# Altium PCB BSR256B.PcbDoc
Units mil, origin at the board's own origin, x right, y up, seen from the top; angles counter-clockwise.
Board outline 2710.5 x 1796.5 mil, 4 copper layers (Top Layer, Signal Layer 1, Signal Layer 2, Bottom Layer), stack 60.434 mil thick; 46 components, 13 nets, 68 pads, 21 vias.
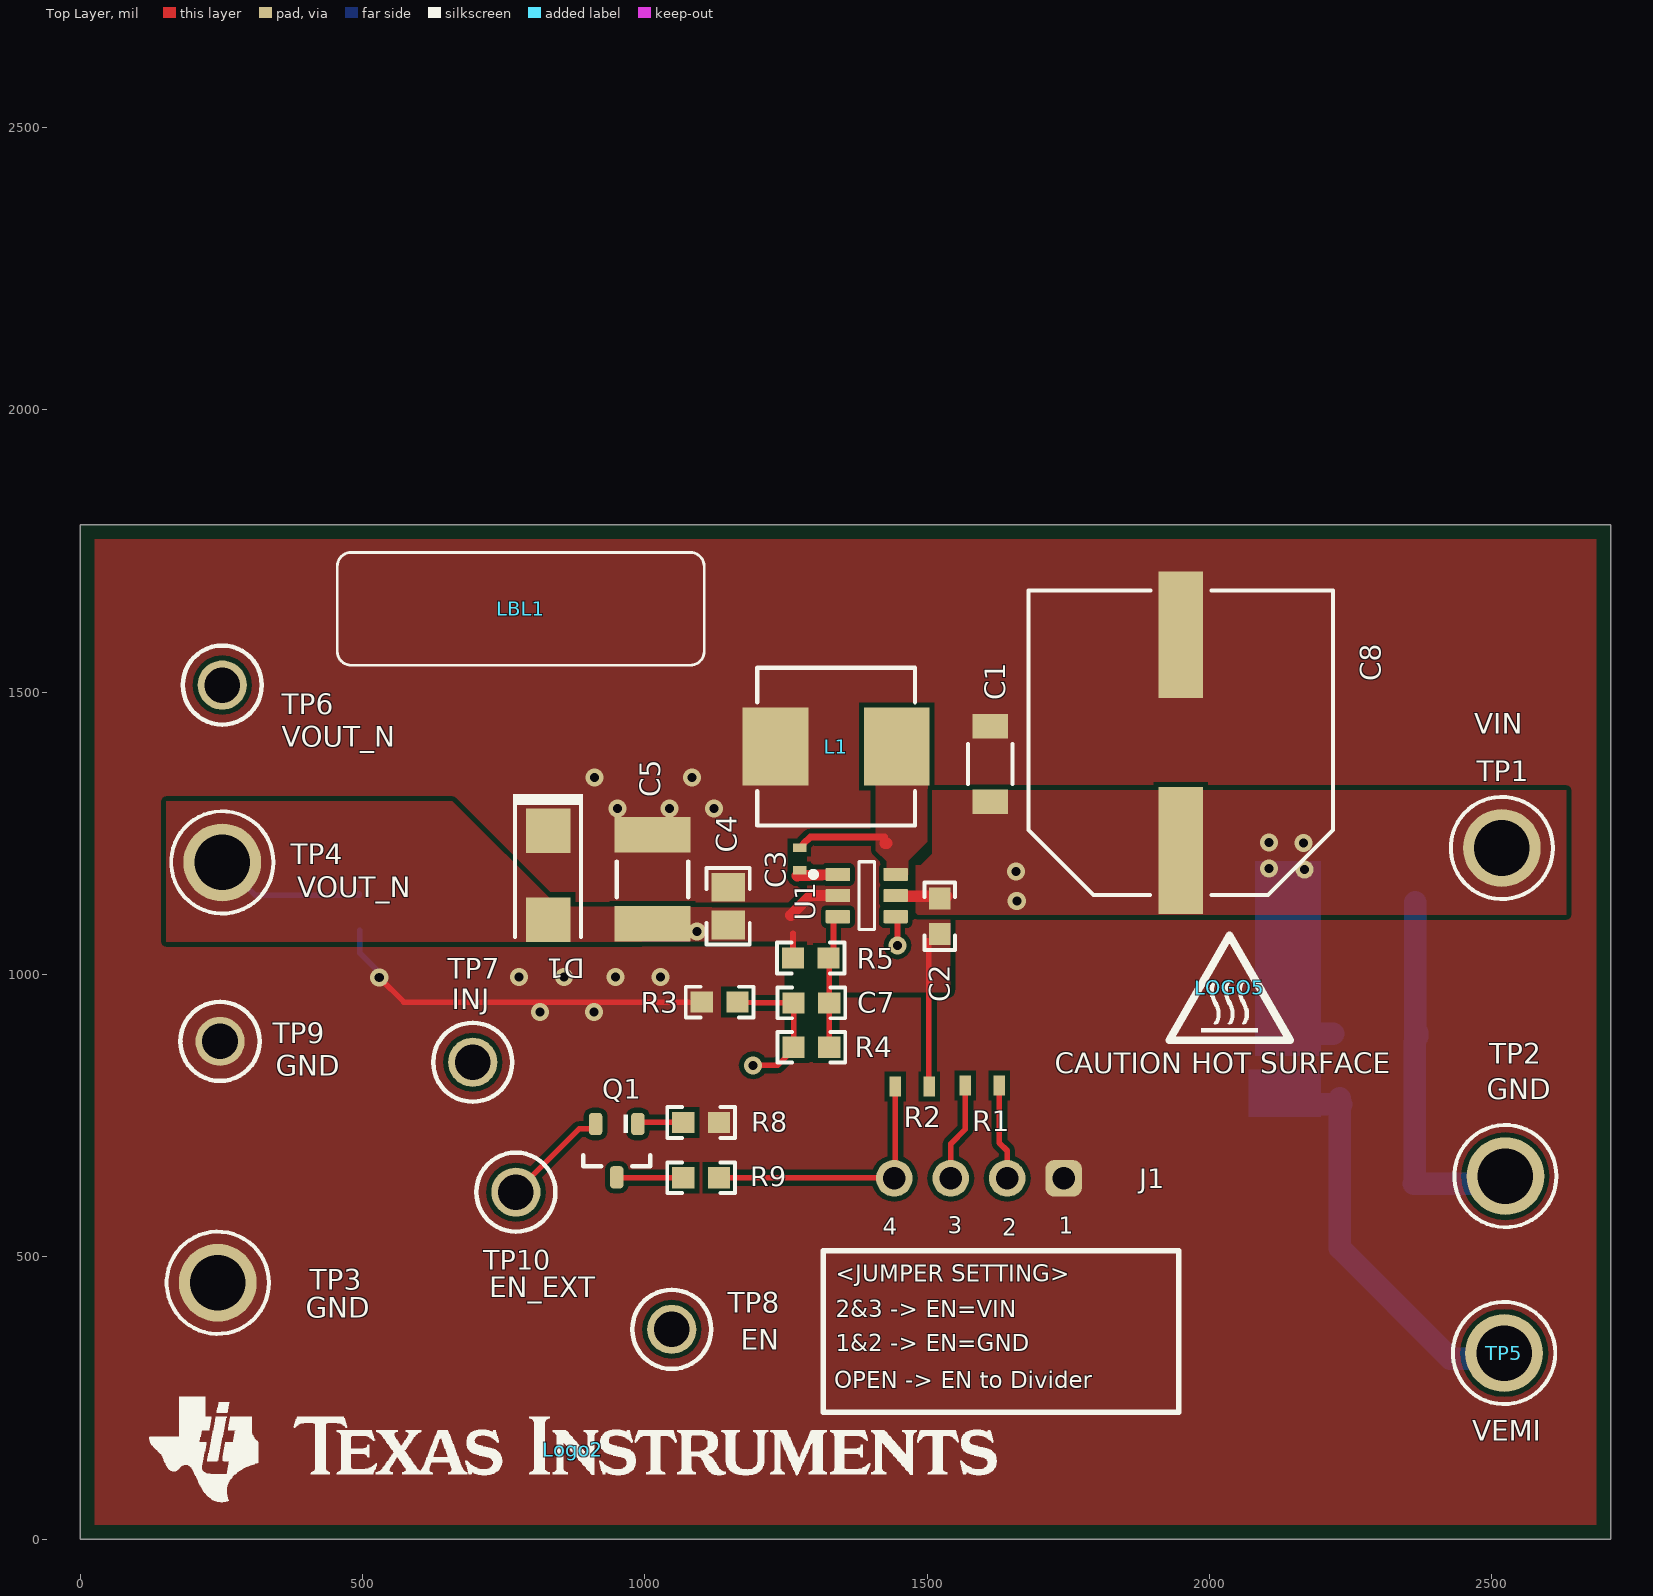
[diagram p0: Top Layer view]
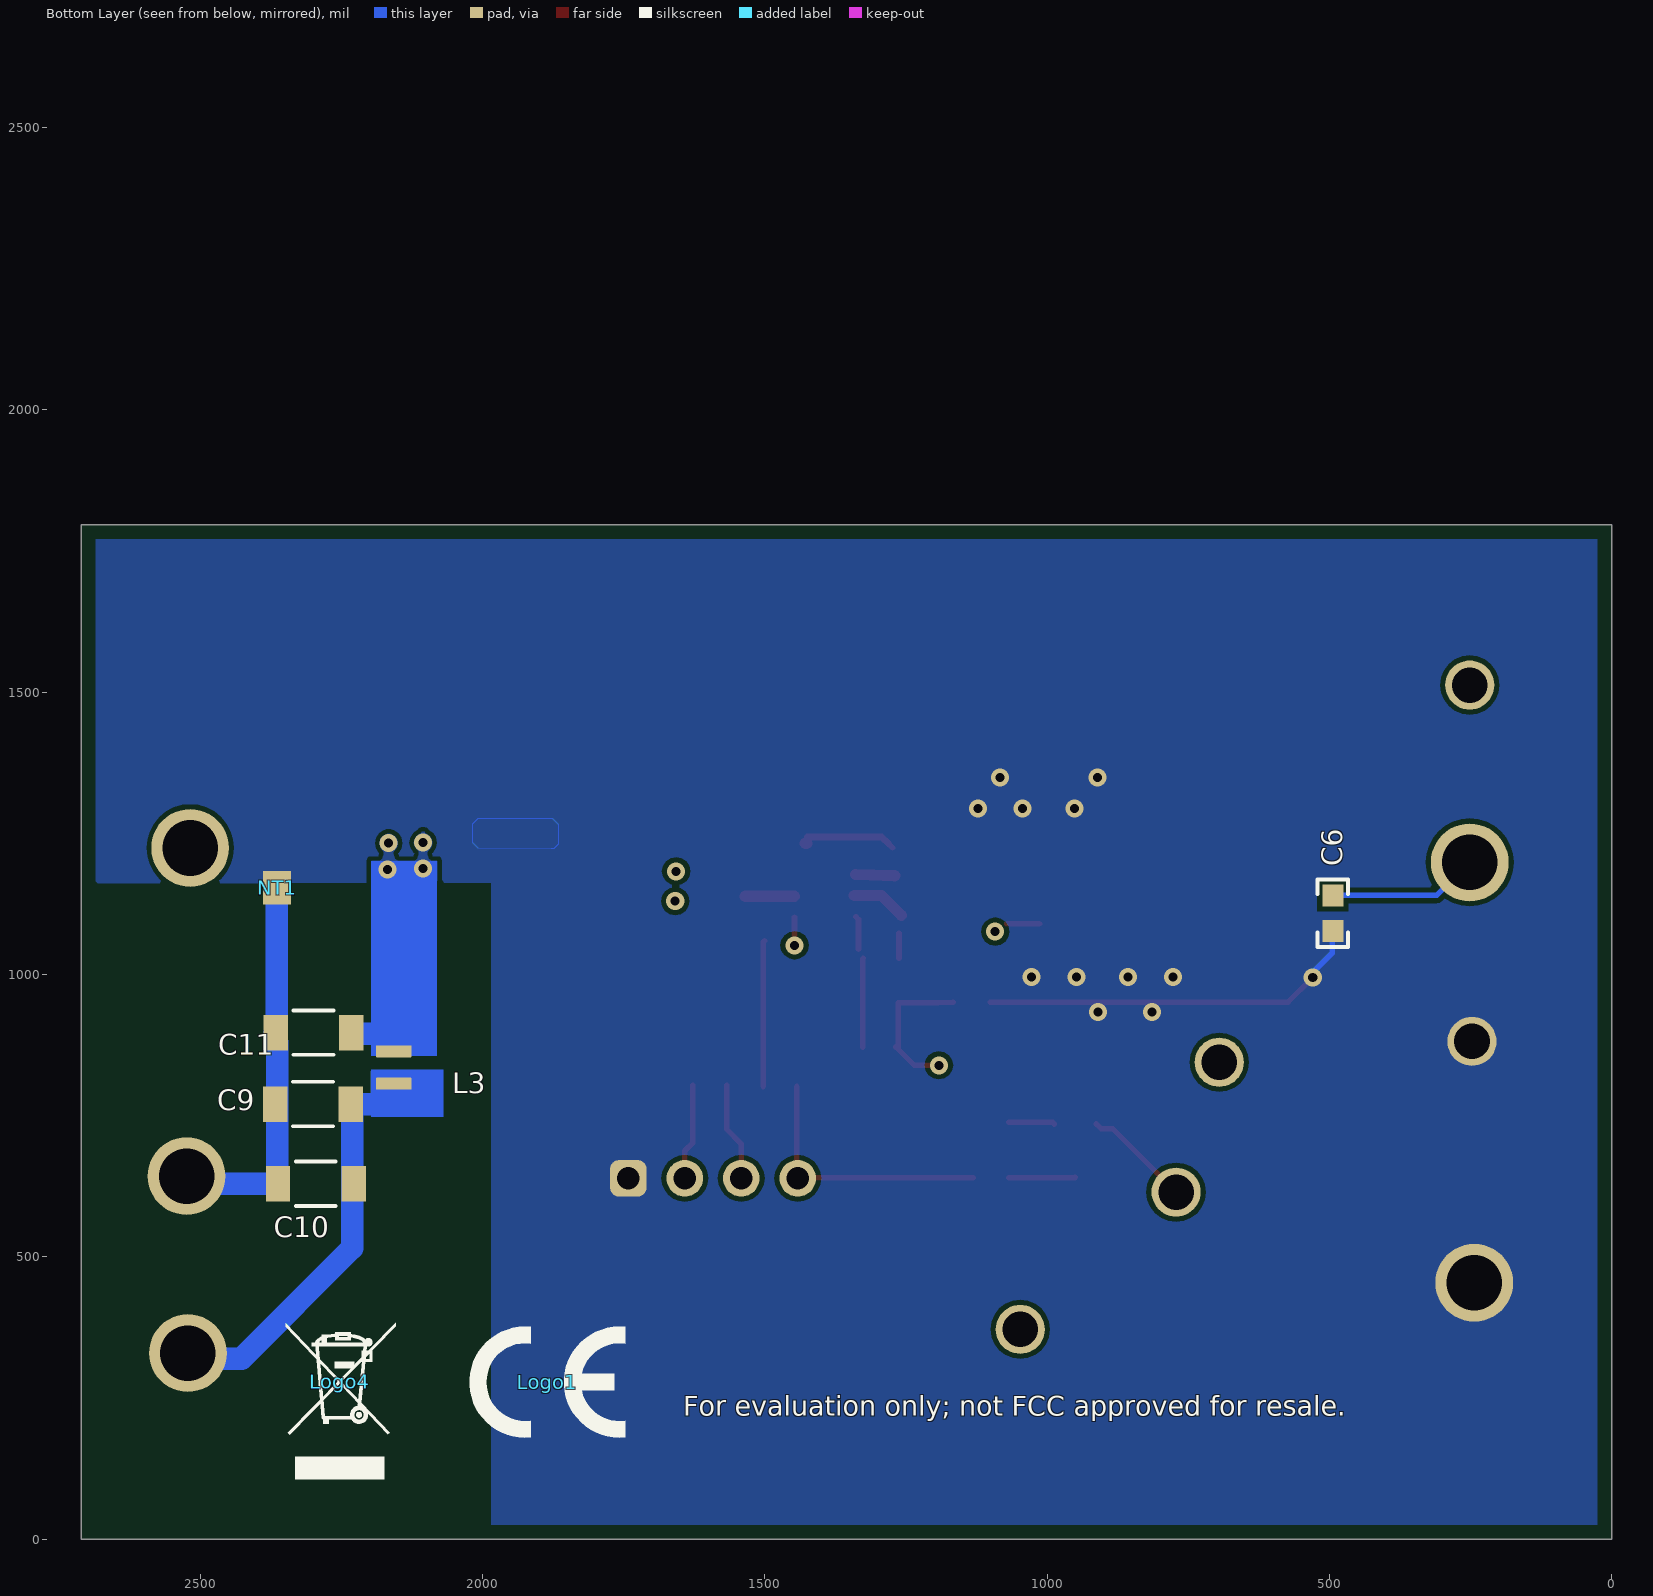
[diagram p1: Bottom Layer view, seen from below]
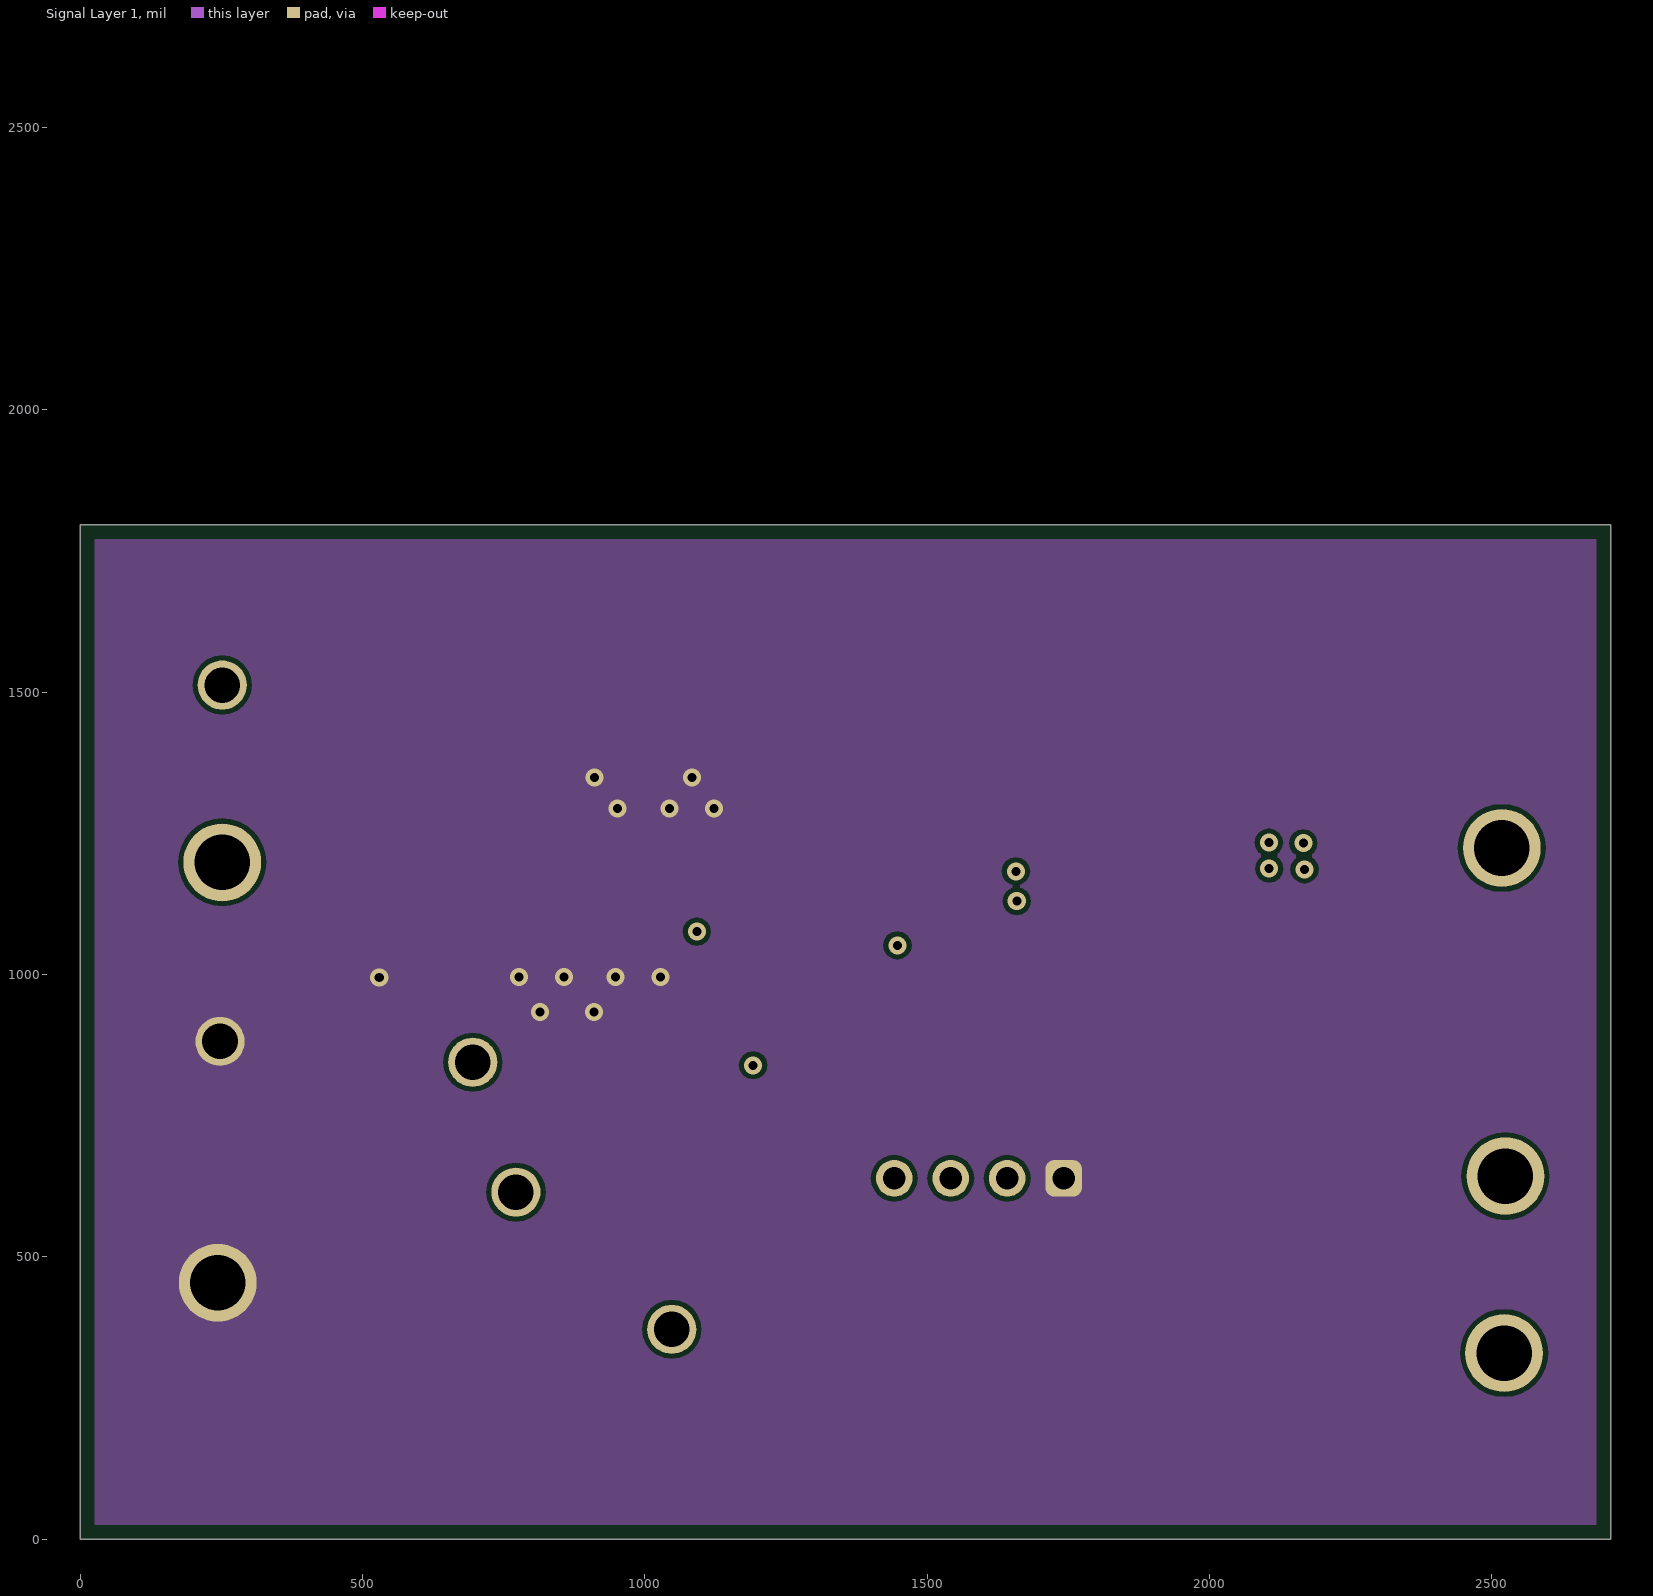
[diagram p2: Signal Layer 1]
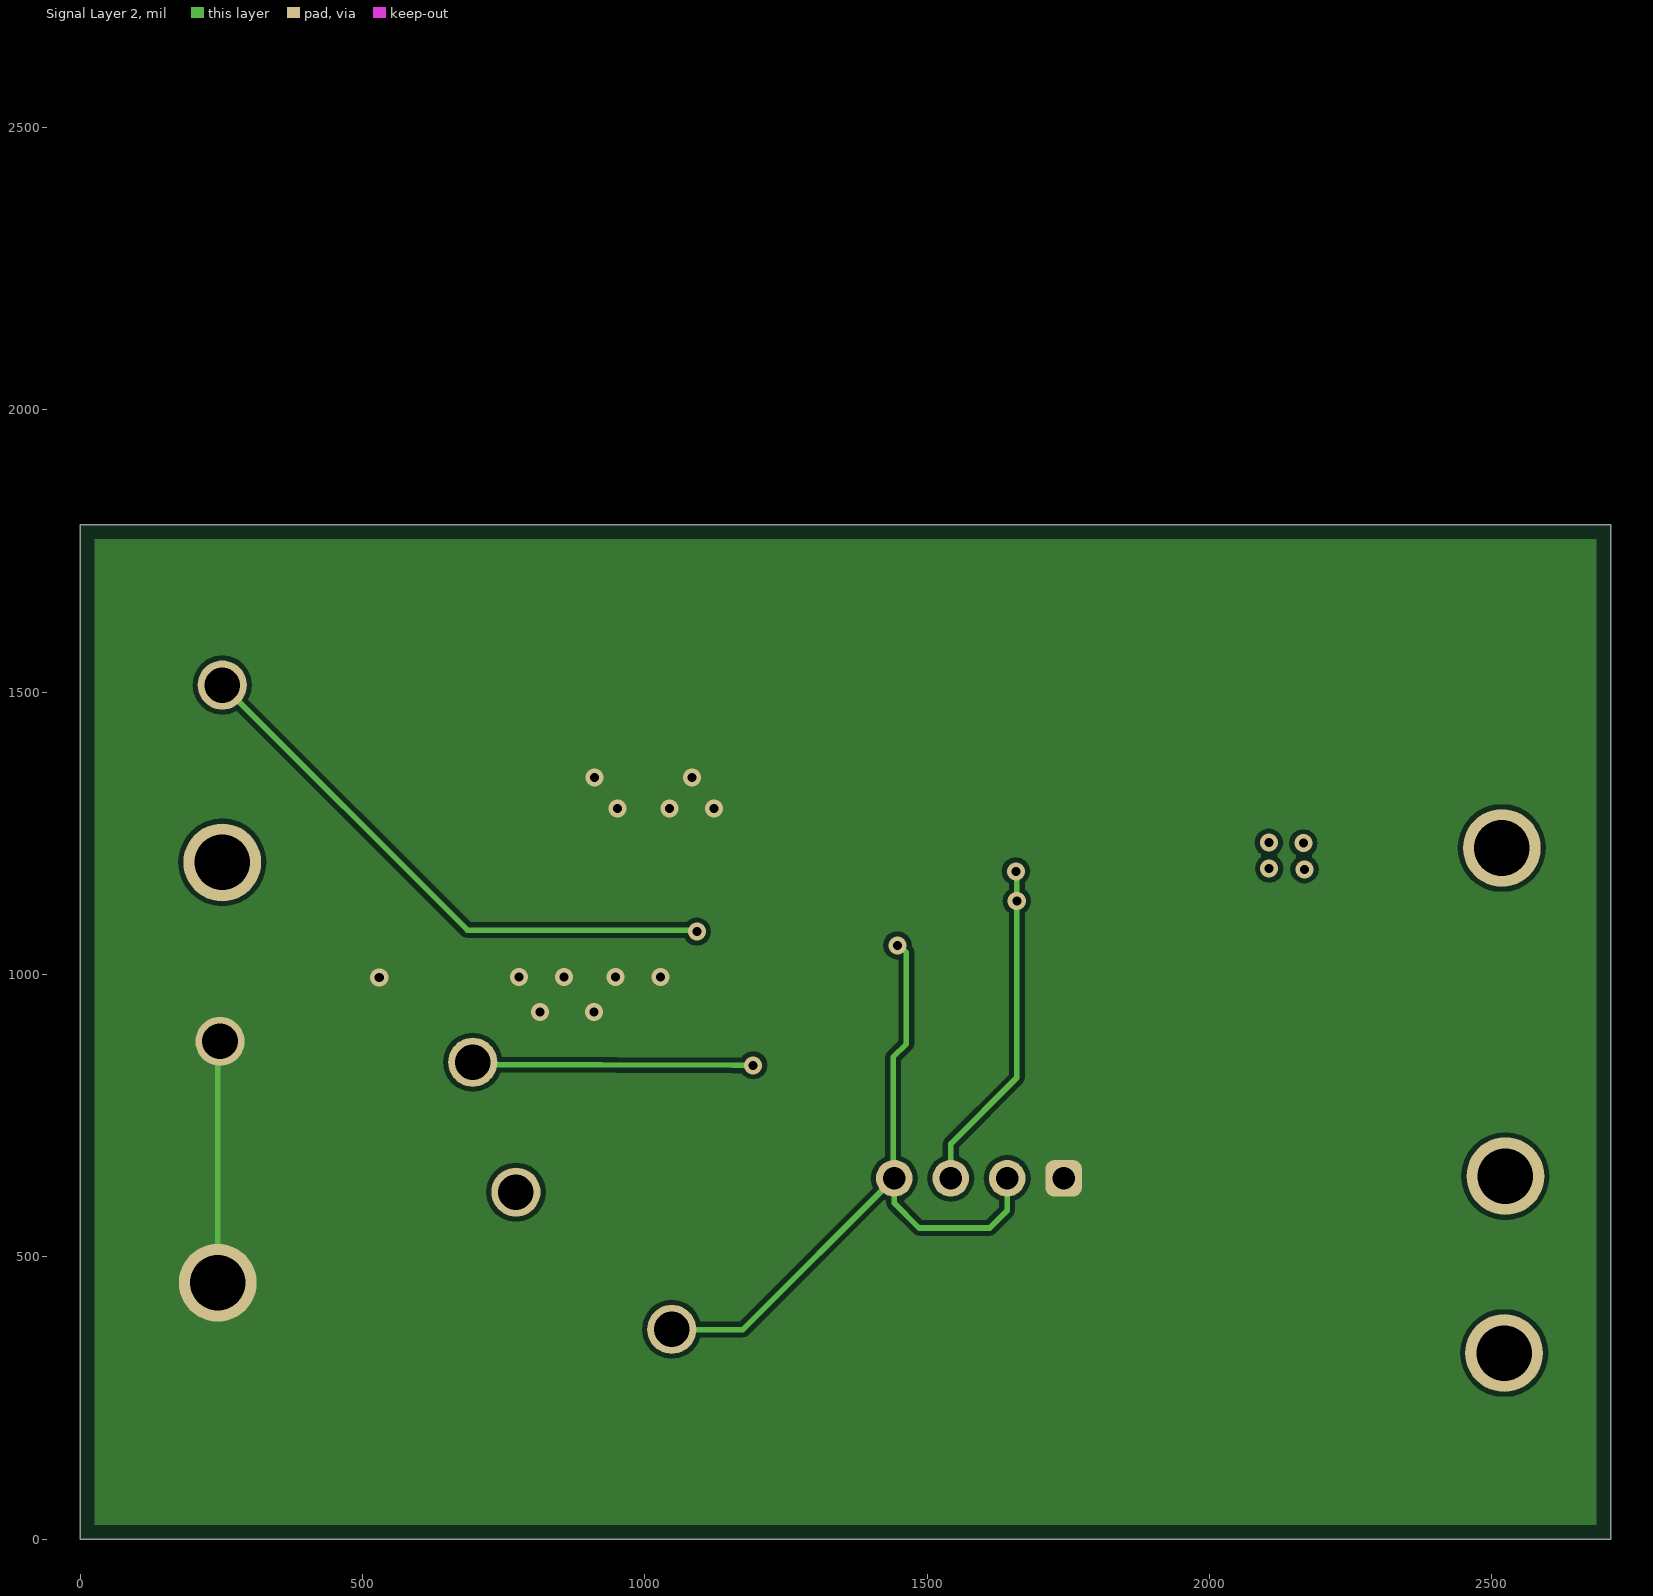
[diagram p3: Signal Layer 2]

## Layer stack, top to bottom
Top Solder: solder mask 0.4, Solder Resist, Dk 3.5
Top Layer: signal copper 2.8
Dielectric1: core 10, FR-4 High Tg, Dk 4.8
Signal Layer 1: signal copper 1.417
Dielectric 2: dielectric 32, FR-4 High Tg, Dk 4.2
Signal Layer 2: signal copper 1.417
Dielectric 3: dielectric 10, FR-4 High Tg, Dk 4.2
Bottom Layer: signal copper 2.8
Bottom Solder: solder mask 0.4, Solder Resist, Dk 3.5

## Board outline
0,0 0,1796.5 2710.5,1796.5 2710.5,0

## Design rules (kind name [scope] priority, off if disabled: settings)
AcuteAngle [All] p1: minimum=4.50000000000000E+0001 checktracksonly=FALSE
AssemblyTestPointUsage [All] p1: valid=2
BoardOutlineClearance BoardOutlineClearance_MountingHoles [OnCopper and InComponentClass('Mounting Holes')] p1: gap=40 ignorepadtopadclearanceinfootprint=FALSE
BoardOutlineClearance BoardOutlineClearance_Poly [OnCopper and IsPoly] p2: gap=25 ignorepadtopadclearanceinfootprint=FALSE
BoardOutlineClearance [OnCopper and Not InComponentClass('Logo') and not InComponentClass('FiducialMark') and not InRegion(1000,500,4000,800) and not InPoly] p3: gap=75 ignorepadtopadclearanceinfootprint=FALSE
Clearance Clearance_Keepouts [((IsTrack Or IsArc) And Not InPoly) And IsFree and IsKeepOut vs ((IsTrack Or IsArc) And Not InPoly) And IsFree and IsKeepOut] p1: gap=7 ignorepadtopadclearanceinfootprint=FALSE
Clearance Clearance_Poly [InPolygon] p2: gap=8.5 ignorepadtopadclearanceinfootprint=FALSE except(0: Arc-Hole Track-Hole SMDPad-Hole THPad-Hole Via-Hole Fill-Hole Poly-Hole Region-Hole Text-Hole)
Clearance [All] p3: gap=7 ignorepadtopadclearanceinfootprint=FALSE except(0: Arc-Arc Arc-Track Arc-SMDPad Arc-THPad Arc-Via Arc-Fill Arc-Poly Arc-Region Arc-Text Arc-Hole)
ComponentClearance ComponentClearance_MountingHoles_FiducialMarks [InComponentClass('Mounting Holes') vs InComponentClass('FiducialMark')] p1: gap=50 collisioncheckmode=3 verticalgap=10 showdistances=FALSE
ComponentClearance ComponentClearance_Shunt [InComponentClass('Header') vs InComponentClass('Shunt')] p2: gap=0 collisioncheckmode=3 verticalgap=0 showdistances=FALSE
ComponentClearance ComponentClearance_Logo [InComponentClass('Logo')] p3: gap=50 collisioncheckmode=3 verticalgap=10 showdistances=FALSE
ComponentClearance ComponentClearance_ScrewToNut [(HasFootprint('NY PMS 440 0025 PH')) vs (HasFootprint('Keystone_1902C'))] p4: gap=5 collisioncheckmode=3 verticalgap=10 showdistances=FALSE
ComponentClearance ComponentClearance_MountingHoles [InComponentClass('Mounting Holes')] p5: gap=250 collisioncheckmode=3 verticalgap=100000 showdistances=FALSE
ComponentClearance ComponentClearance_SmallPassives [HasFootprint('0201*') or HasFootprint('0402*') or HasFootprint('0508') or HasFootprint('0603*') or HasFootprint('0612') or HasFootprint('0805*') or HasFootprint('0815*') or HasFootprint('0830*') or HasFootprint('1206*') or HasFootprint('1210*') or HasFootprint('1808*') or HasFootprint('1812*') or HasFootprint('1825*') or HasFootprint('2010*') or HasFootprint('2220*') or HasFootprint('2225*') or HasFootprint('2512*') or HasFootprint('2728*') or HasFootprint('3518*') vs HasFootprint('0201*') or HasFootprint('0402*') or HasFootprint('0508') or HasFootprint('0603*') or HasFootprint('0612') or HasFootprint('0805*') or HasFootprint('0815*') or HasFootprint('0830*') or HasFootprint('1206*') or HasFootprint('1210*') or HasFootprint('1808*') or HasFootprint('1812*') or HasFootprint('1825*') or HasFootprint('2010*') or HasFootprint('2220*') or HasFootprint('2225*') or HasFootprint('2512*') or HasFootprint('2728*') or HasFootprint('3518*')] p6: gap=14.96 collisioncheckmode=3 verticalgap=10 showdistances=FALSE
ComponentClearance ComponentClearance_THtoSMT [IsThruComponent vs IsSMTComponent] p7: gap=10 collisioncheckmode=3 verticalgap=30 showdistances=FALSE
ComponentClearance ComponentClearance_THtoTH [IsThruComponent vs IsThruComponent] p8: gap=30 collisioncheckmode=3 verticalgap=30 showdistances=FALSE
ComponentClearance [All] p9: gap=30 collisioncheckmode=3 verticalgap=10 showdistances=FALSE
DiffPairsRouting [All] p1: maxlimit=100 minlimit=10 mostfreqgap=10 toplayer_minwidth=15 toplayer_maxwidth=15 toplayer_prefwidth=15 midlayer1_minwidth=15 midlayer1_maxwidth=15 midlayer1_prefwidth=15 midlayer2_minwidth=15 midlayer2_maxwidth=15 midlayer2_prefwidth=15 bottomlayer_minwidth=15 bottomlayer_maxwidth=15 bottomlayer_prefwidth=15 maxuncoupledlength=1000
FabricationTestPointUsage TestPointUsage [All] p1: valid=2 allowmultiple=FALSE
FabricationTestpoint Testpoint [All] p1: side=3 testpointundercomponent=TRUE minsize=40 maxsize=100 preferedsize=60 minholesize=0 maxholesize=40 preferedholesize=32 testpointgrid=1 allowsidetop=TRUE allowsidebottom=TRUE usegrid=TRUE gridtolerance=0.01
FanoutControl Fanout_LCC [IsLCC] p1: bgadir=Out bgaviamode=Centered fanoutstyle=Auto fanoutdirection=Alternating viagrid=1 // Fanout_LCC (Default Rule)
FanoutControl Fanout_BGA [IsBGA] p2: bgadir=Out bgaviamode=Centered fanoutstyle=Auto fanoutdirection=Alternating viagrid=1 // Fanout_BGA (Default Rule)
FanoutControl Fanout_Default [All] p4: bgadir=Out bgaviamode=Centered fanoutstyle=Auto fanoutdirection=Alternating viagrid=1 // Fanout_Default (Default Rule)
FanoutControl Fanout_Small [(CompPinCount < 5)] p5: bgadir=Out bgaviamode=Centered fanoutstyle=Auto fanoutdirection=OutThenIn viagrid=1 // Fanout_Small (Default Rule)
HoleSize [All] p1: absolutevalues=TRUE maxlimit=251 minlimit=7.87 maxpercent=80.000 minpercent=20.000
MinimumAnnularRing MinimumAnnularRing_ThermalPadVias [IsVia and InAnyComponent] p1: minimumring=5.91
MinimumAnnularRing [All] p2: minimumring=8
MinimumSolderMaskSliver MinimumSolderMaskSliver_Logo [InComponentClass('Logo') vs InComponentClass('Logo')] p1: minsoldermaskwidth=0.7
MinimumSolderMaskSliver [All] p2: minsoldermaskwidth=3.94
PlaneClearance [All] p1: clearance=0
PlaneConnect [All] p1: planeconnectstyle=Direct reliefexpansion=10 reliefentries=2 reliefconductorwidth=10 reliefairgap=10
PolygonConnect [All] p1: connectstyle=Direct reliefconductorwidth=10 reliefentries=4 polygonreliefangle="90 Angle" airgapwidth=10
RoutingVias ThermalPadVias [IsVia and InAnyComponent] p1: holewidth=7.87 width=19.68 viastyle="Through Hole" minholewidth=7.87 minwidth=19.68 maxholewidth=12.99 maxwidth=23.62
RoutingVias [All] p2: holewidth=16 width=34 viastyle="Through Hole" minholewidth=7.87 minwidth=26 maxholewidth=40 maxwidth=65
SilkToBoardRegionClearance [Not ((IsComment or IsDesignator) And (Hide <> 'False')) and not InRegion(1000,500,4000,800)] p1:
SilkToSilkClearance SilkToSilkClearance_Pb-FreeLogo [(HasFootprint('Pb-Free_Overlay_Medium') OR HasFootprint('Pb-Free_Overlay_Small')) vs (HasFootprint('Pb-Free_Overlay_Medium') OR HasFootprint('Pb-Free_Overlay_Small'))] p1: silktosilkclearance=0
SilkToSilkClearance [All] p2: silktosilkclearance=4
SilkToSolderMaskClearance SilkToComponentPadClearance [(IsPad or IsFill or IsRegion) and InAnycomponent] p1: minsilkscreentomaskgap=2 clearancetoexposedcopper=TRUE
SilkToSolderMaskClearance "Silk to Solder Mask Opening" [All] p2: minsilkscreentomaskgap=0.5 clearancetoexposedcopper=TRUE
SolderMaskExpansion [All] p1: expansion=1.85
Width [All] p1: maxlimit=100 minlimit=3 preferedwidth=10 midlayer1_minwidth=6 midlayer2_minwidth=6 bottomlayer_minwidth=6 minimp=50.000000 maximp=50.000000 favimp=50.000000 checkconnectedcopper=TRUE
14 further rules are at their usual default settings.

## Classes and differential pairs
component class BSR256B: C1 C2 C3 C4 C5 C6 C7 C8 C9 C10 C11 D1 J1 L1 L3 NT1 Q1 R1 R2 R3 R4 R5 R8 R9 TP1 TP2 TP3 TP4 TP5 TP6 TP7 TP8 TP9 TP10 U1
component class Label: LBL1
component class BSR256B_Hardware: LBL1 Logo1 Logo2 Logo3 Logo4 LOGO5 LOGO7 ZZ1 ZZ2 ZZ3 ZZ4 ZZ5
component class Logo: Logo2
component class Header: J1
component class AssemblyNote: ZZ1 ZZ2 ZZ3 ZZ4 ZZ5

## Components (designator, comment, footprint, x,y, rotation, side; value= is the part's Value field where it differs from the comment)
C1 "C3216X7S2A225K160AB" 1206_180 1611.5,1372.5 r90 top value=2.2uF
C2 "GRM188R72A104KA35J" 0603 1522,1103.14 r270 top value=0.1uF
C3 "GRM155R71E104KE14D" 0402S 1273.81,1204.5 r270 top value=0.1uF
C4 "GRM21BZ71E106KE15L" 0805 1147.5,1120.96 r270 top value=10uF
C5 "CGA8P1X7R1E226M250KC" 1812_280 1013.31,1168.5 r270 top value=22uF
C6 "C1608X7R1H104K080AA" 0603 493.93,1108.5 r90 bottom value=0.1uF
C7 "CGA3E2C0G1H220J080AA" 0603 1294.72,949.6 r0 top value=22pF
C8 "EEV-TG2A470Q" Panasonic_H13 1949,1410.5 r90 top value=47uF
C9 "C3216X7S2A225K160AB" 1206_180 2300.03,770.5 r0 bottom value=2.2uF
C10 "C3216X7S2A225K160AB" 1206_180 2295.03,629.24 r0 bottom value=2.2uF
C11 "C3216X7S2A225K160AB" 1206_180 2299.1,897 r0 bottom value=2.2uF
D1 "B260A-13-F" SMA 828.5,1176 r270 top value=60V
J1 "TSW-104-07-G-S" TSW-104-07-G-S 1591.52,639 r180 top
L1 "74437349150" WE-LHMI_7050 1338.5,1403.5 r180 top value=15uH
L3 "DFE201612E-1R0M=P2" DFE201612E 2157.03,835.24 r90 bottom value=1uH
LBL1 "THT-14-423-10" Label_650x200 780,1647.5 r0 top
Logo1 "CE Mark" CE_Mark_5mm 1885,278 r180 bottom
Logo2 "Texas Instruments" TI_Horizontal_Overlay_Medium 872.5,158.5 r0 top
Logo3 "FCC disclaimer" FCC_disclaimer -358.76,747 r90 bottom
Logo4 "WEEE logo" WEEE_Minimum 2252.5,278.5 r180 bottom
LOGO5 "CAUTION HOT SURFACE" IEC_HotSurface_Small 2035.5,976.5 r0 top
NT1 "Net-Tie" Net-Tie_50milWide_30milLong 2363.5,1153.5 r90 bottom net-tie
Q1 "CMPT3906 LEAD FREE" SOT-23 950,688 r270 top value="40 V"
R1 "CRCW0603402KFKEA" 0603S 1597.5,803.5 r180 top value=402k
R2 "CRCW0603133KFKEA" 0603S 1473.5,801.5 r0 top value=133k
R3 "Resistor" 0603 1132.22,950.99 r0 top value=49.9
R4 "CRCW060388K7FKEA" 0603 1294.72,871.17 r180 top value=88.7k
R5 "RC0603FR-0722K1L" 0603 1293.7,1029 r0 top value=22.1k
R8 "ERJ-3EKF1002V" 0603 1099.5,738 r180 top value=10.0k
R9 "ERJ-3EKF1002V" 0603 1099.5,640 r180 top value=10.0k
TP1 "1502-2" Keystone1502-2 2517.5,1224 r0 top
TP2 "1502-2" Keystone1502-2 2523.77,642.8 r0 top
TP3 "1502-2" Keystone1502-2 243.5,454 r0 top
TP4 "1502-2" Keystone1502-2 251.5,1198.5 r0 top
TP5 "1502-2" Keystone1502-2 2521.5,329.5 r0 top
TP6 "5010" Keystone5010 251.5,1512.5 r0 top
TP7 "5014" Keystone5014 695,844.5 r0 top
TP8 "5014" Keystone5014 1047.5,371.5 r0 top
TP9 "5011" Keystone5011 247.5,881.5 r0 top
TP10 "5014" Keystone5014 771.5,614.5 r0 top
U1 "LMR51610DBVR" DBV0006A-MFG 1392.84,1139.74 r0 top
ZZ1 "This Assembly Note is for PCB labels only" AssemblyNoteLabel 197,3292.5 r0 top
ZZ2 "These assemblies are ESD sensitive, ESD precautions shall be observed." AssemblyNote 197,3169.5 r0 top
ZZ3 "These assemblies must be clean and free from flux and all contaminants. Use of no clean flux is not acceptable." AssemblyNote 197,3046 r0 top
ZZ4 "These assemblies must comply with workmanship standards IPC-A-610 Class 2, unless otherwise specified." AssemblyNote 197,2913.5 r0 top
ZZ5 "SH-J1 should be put in the 2 & 3 pin of JP1 by default." AssemblyNote 197,2800.5 r0 top

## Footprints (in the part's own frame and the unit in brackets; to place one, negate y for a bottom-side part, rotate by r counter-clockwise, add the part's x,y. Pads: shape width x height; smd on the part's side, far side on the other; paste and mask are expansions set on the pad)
0402S [mil] "Based on C0402S footprint from PADS legacy"
  rect 15x24 smd: 1(-20,0) 2(20,0)
  body extent -22,-12 22,12, height 24
0603 [mm] "0603 from SM-752 data"
  rect 1x0.95 smd: 1(-0.8,0) 2(0.8,0)
  silkscreen extent -1.52,-0.69 1.52,0.69, body extent -0.87,-0.47 0.87,0.47, height 1
0603S [mil]
  rect 20x35 smd: 1(-30,0) 2(30,0)
  body extent -34,-19 34,19, height 39
0805 [mm] "0805 from SM-752 data"
  rect 1.3x1.5 smd: 1(-0.85,0) 2(0.85,0)
  silkscreen extent -1.72,-0.97 1.72,0.97, body extent -1.1,-0.72 1.1,0.72, height 1.45
1206_180 [mm] "1206_180"
  rect 1.1x1.6 smd: 1(-1.7,0) 2(1.7,0)
  silkscreen extent -0.9,-1 0.9,1, body extent -1.75,-0.95 1.75,0.95, height 1.8
1812_280 [mm] "1812"
  rect 1.6x3.4 smd: 1(-2,0) 2(2,0)
  silkscreen extent -0.8,-1.6 0.8,1.6, body extent -2.4,-1.7 2.4,1.7, height 2.8
AssemblyNote [mil] "Assembly Note"
AssemblyNoteLabel [mil] "Assembly Note for PCB Labels"
CE_Mark_5mm [mil] "Minimum text height for CE Mark"
  silkscreen extent -138,-98 138,98
DBV0006A-MFG [mm]
  rrect17% 1.1x0.6 smd paste+0 mask+0: 1(-1.3,0.95) 2(-1.3,0) 3(-1.3,-0.95) 4(1.3,-0.95) 5(1.3,0) 6(1.3,0.95)
  silkscreen extent -2.52,-1.53 0.35,1.53, body extent -1.95,-1.78 1.95,1.78, height 0.25
DFE201612E [mm] "MuRata recommended"
  rrect18% 0.55x1.6 smd: 1(-0.725,0) 2(0.725,0)
  body extent -1.1,-0.9 1.1,0.9, height 1.2
FCC_disclaimer [mil]
IEC_HotSurface_Small [mil]
  silkscreen extent -107,-93 107,92
Keystone1502-2 [mm] "Double Turret"
  round 3.5 hole 2.5: 1(0,0)
  silkscreen extent -2.3,-2.3 2.3,2.3, body extent -1.6,-1.6 1.59,1.6, height 5.62
Keystone5010 [mil] "Keystone Multipurpose loops"
  round 87 hole 63: 1(0,0)
  silkscreen extent -70,-70 70,70, body extent -63,-63 63,62, height 319
Keystone5011 [mil] "Keystone Multipurpose loops"
  round 87 hole 63: 1(0,0)
  silkscreen extent -70,-70 70,70, body extent -63,-63 63,62, height 319
Keystone5014 [mil] "Keystone Multipurpose loops"
  round 87 hole 63: 1(0,0)
  silkscreen extent -70,-70 70,70, body extent -63,-63 63,62, height 319
Label_650x200 [mil] "Thermal Transfer Label"
  round 1 on Mech13: 0(0,0)
  silkscreen extent -325,-100 325,100, body extent -325,-100 325,100, height 1
Net-Tie_50milWide_30milLong [mil] "50mil net tie, no solder mask opening, no solder paste"
  rect 30x50 smd paste-20 mask-20: 1(-15,0) 2(15,0)
Panasonic_H13 [mm] "12.5 x 13.5mm:  Panasonic H13"
  rect 5.7x2 smd: 1(-4.85,0) 2(4.85,0)
  silkscreen extent -6.85,-6.85 6.85,6.85, body extent -6.9,-6.75 6.9,6.75, height 13.5
SMA [mm] "Molded Diode, 2-Leads, Body 4.3x2.6mm, IPC Medium Density, based on OnSemi component dimensions and land pattern"
  rect 2x2 smd: 1(-2,0) 2(2,0)
  silkscreen extent -3.66,-1.57 2.79,1.57, body extent -2.6,-1.3 2.6,1.3, height 2.42
SOT-23 [mm] "SOT23, 3-Leads, Body 2.9x1.3mm, Pitch 0.95mm, Lead Span 2.5mm, IPC Medium Density"
  rrect50% 1x0.6 smd: 1(-1.2,0.95) 2(-1.2,-0.95) 3(1.2,0)
  silkscreen extent -1.63,-1.5 0.7,1.5, body extent -1.16,-1.45 1.21,1.45, height 1
TI_Horizontal_Overlay_Medium [mil]
  silkscreen extent -750,-94 750,94
TSW-104-07-G-S [mm] "Samtec 100mil, 1x4, 230 mil above insulator"
  rrect50% 1.65x1.65 hole 1.016: 1(-3.81,0)
  round 1.65 hole 1.016: 2(-1.27,0) 3(1.27,0) 4(3.81,0)
  body extent -5.08,-1.27 5.08,1.27, height 8.38
WE-LHMI_7050 [mm] "Wurth"
  rect 2.95x3.5 smd: 1(-2.725,0) 2(2.725,0)
  silkscreen extent -3.55,-3.55 3.55,3.55, body extent -3.8,-3.45 3.8,3.45, height 5
WEEE_Minimum [mil] "WEEElie bin"
  silkscreen extent -95,-172 99,104

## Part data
C1 C9 C10 C11: library part CMP-0008724-2, "CAP, CERM, 2.2 uF, 100 V, +/- 10%, X7S, 1206", Cap_Case=1206_180, Manufacturer=TDK, Supplier Part Number 1=445-5207-1-ND, TempCo=X7S, Tolerance_%=10%, Value1="0.005718 ohm", Value2=100V, ValueDisplayed=2.2uF
C2: library part CMP-0007470-5, "CAP, CERM, 0.1 uF, 100 V, +/- 10%, X7R, 0603", Cap_Case=0603, Manufacturer=MuRata, Supplier Part Number 1=490-6439-1-ND, TempCo=X7R, Tolerance_%=10%, Value1=Unknown, Value2=100V, ValueDisplayed=0.1uF
C3: library part CMP-0006659-1, "CAP, CERM, 0.1 uF, 25 V, +/- 10%, X7R, 0402", Cap_Case=0402, Manufacturer=MuRata, Supplier Part Number 1=490-10698-1-ND, TempCo=X7R, Tolerance_%=10%, Value1=Unknown, Value2=25V, ValueDisplayed=0.1uF
C4: library part CMP-0008378-2, "CAP, CERM, 10 uF, 25 V, +/- 10%, X7R, 0805", Cap_Case=0805, Manufacturer=MuRata, Supplier Part Number 1=81-GRM21BZ71E106KE5L, TempCo=X7R, Tolerance_%=10%, Value1=Unknown, Value2=25V, ValueDisplayed=10uF
C5: library part CMP-0009402-2, "CAP, CERM, 22 uF, 25 V, +/- 20%, X7R, AEC-Q200 Grade 1,", Cap_Case=1812_280, Manufacturer=TDK, Supplier Part Number 1=445-7910-1-ND, TempCo=X7R, Tolerance_%=20%, Value1="0.002434 ohm", Value2=25V, ValueDisplayed=22uF
C6: library part CMP-0007044-3, "CAP, CERM, 0.1 uF, 50 V, +/- 10%, X7R, 0603", Cap_Case=0603, Manufacturer=TDK, Supplier Part Number 1=445-1314-1-ND, TempCo=X7R, Tolerance_%=10%, Value1="0.0296 ohm", Value2=50V, ValueDisplayed=0.1uF
C7: library part CMP-0007071-3, "CAP, CERM, 22 pF, 50 V, +/- 5%, C0G/NP0, AEC-Q200 Grade 1, 0603", Cap_Case=0603, Manufacturer=TDK, Supplier Part Number 1=445-5632-1-ND, TempCo=C0G/NP0, Tolerance_%=5%, Value1=Unknown, Value2=50V, ValueDisplayed=22pF
C8: library part CMP-0011227-2, "CAP, AL, 47 uF, 100 V, +/- 20%, 0.42 ohm, AEC-Q200 Grade 1, SMD", Cap_Case=12.5x13.5mm, Manufacturer=Panasonic, Supplier Part Number 1=PCE3701CT-ND, Tolerance_%=20%, Value1="0.42 ohm", Value2=100V, ValueDisplayed=47uF
D1: library part CMP-0028407-1, "Diode, Schottky, 60 V, 2 A, SMA", Manufacturer="Diodes Inc.", Supplier Part Number 1=B260A-FDICT-ND, Value1=2A, Value2=0.7V
J1: library part CMP-0075409-2, "Header, 100mil, 4x1, Gold, TH", Color=Black, Current_A=6.3A, Manufacturer=Samtec, Supplier Part Number 1=SAM1029-04-ND, Voltage_V=550V
L1: library part CMP-0064491-2, "Inductor, Shielded Drum Core, Powdered Iron, 15 uH, 2.75 A, 0.092 ohm, SMD", Manufacturer="Wurth Elektronik", Supplier Part Number 1=710-74437349150, Value1="0.092 ohm", Value2=2.75A, ValueDisplayed=15uH
L3: library part CMP-0080773-1, "Inductor, Shielded, Metal Composite, 1 µH, 2.9 A, 0.048 ohm, SMD", Manufacturer=MuRata, PartNumber=DFE201612E-1R0M{}P2, Value1="0.048 ohm", Value2=2.9A, ValueDisplayed=1µH
LBL1: library part CMP-0003625-1, "Thermal Transfer Printable Labels, 0.650\" W x 0.200\" H - 10,000 per roll", Manufacturer=Brady, Supplier Part Number 1=97C5133
Logo1: library part CMP-0074844-1
Logo2: library part CMP-0074838-1, "Texas Instrument Corporate Signature"
Logo3: library part CMP-0074847-1, "FCC_disclaimer"
Logo4: library part CMP-0074769-1
LOGO5: library part CMP-0074837-1, "IEC 61010-1 Hot Surface Warning"
NT1: library part CMP-0078142-2, "Single point connection between nets.", Manufacturer=N/A
Q1: library part CMP-0000320-1, "Transistor, PNP, 40 V, 0.2 A, SOT-23", Manufacturer="Central Semiconductor", Supplier Part Number 1=610-CMPT3906, Value1="0.2 A"
R1: library part CMP-0022408-4, "RES, 402 k, 1%, 0.1 W, AEC-Q200 Grade 0, 0603", Manufacturer=Vishay-Dale, Power_W=100mW, Supplier Part Number 1=541-402KHCT-ND, TempCo="100 ppm/C", Tolerance_%=1%, Value2=0.1W, Value_Code=402k
R2: library part CMP-0022038-4, "RES, 133 k, 1%, 0.1 W, AEC-Q200 Grade 0, 0603", Manufacturer=Vishay-Dale, Power_W=100mW, Supplier Part Number 1=541-133KHCT-ND, TempCo="100 ppm/C", Tolerance_%=1%, Value2=0.1W, Value_Code=133k
R3: library part CMP-0022448-3, "RES, 49.9, 1%, 0.1 W, 0603", Manufacturer=Vishay-Dale, PartNumber=CRCW060349R9FKEA, Power_W=100mW, Supplier Part Number 1=541-49.9HCT-ND, TempCo="100 ppm/C", Tolerance_%=1%, Value2=0.1W, Value_Code=49R9, ValueDisplayed=49.9
R4: library part CMP-0022632-2, "RES, 88.7 k, 1%, 0.1 W, 0603", Manufacturer=Vishay-Dale, Power_W=100mW, Supplier Part Number 1=541-88.7KHCT-ND, TempCo="100 ppm/C", Tolerance_%=1%, Value2=0.1W, Value_Code=88k7, ValueDisplayed=88.7k
R5: library part CMP-0022923-5, "RES, 22.1 k, 1%, 0.1 W, 0603", Manufacturer=Yageo, Power_W=100mW, Supplier Part Number 1=311-22.1KHRCT-ND, TempCo="100 ppm/C", Tolerance_%=1%, Value2=0.1W, Value_Code=22k1, ValueDisplayed=22.1k
R8 R9: library part CMP-0022684-2, "RES, 10.0 k, 1%, 0.1 W, 0603", Manufacturer=Panasonic, Power_W=100mW, Supplier Part Number 1=P10.0KHCT-ND, TempCo="100 ppm/C", Tolerance_%=1%, Value2=0.1W, Value_Code=10k0, ValueDisplayed=10.0k
TP1 TP2 TP3 TP4 TP5: library part CMP-0055113-1, "Terminal, Turret, TH, Double", Manufacturer=Keystone, Supplier Part Number 1=36-1502-2-ND
TP6: library part CMP-0055147-1, "Test Point, Multipurpose, Red, TH", Color=Red, Manufacturer=Keystone, Supplier Part Number 1=36-5010-ND
TP7 TP8 TP10: library part CMP-0055151-1, "Test Point, Multipurpose, Yellow, TH", Color=Yellow, Manufacturer=Keystone, Supplier Part Number 1=36-5014-ND
TP9: library part CMP-0055148-1, "Test Point, Multipurpose, Black, TH", Color=Black, Manufacturer=Keystone, Supplier Part Number 1=36-5011-ND
U1: library part CMP-0096066-1, "65V, 1A Synchronous Step-Down DC-DC Converter", Manufacturer="Texas Instruments", Max Supply Voltage=65V, Min Supply Voltage=4V, Nominal Supply Current=25-420uA, Operating Temperature Range="-40°C to +150°C", Output Voltage=0.8-28V, Switching Frequency=400/1100kHz
ZZ1: library part CMP-0003616-3
ZZ2: library part CMP-0077236-1
ZZ3: library part CMP-0077237-1
ZZ4: library part CMP-0077238-1
ZZ5: library part CMP-0077238-1, "These assemblies must comply with workmanship standards IPC-A-610 Class 2, unless otherwise specified."

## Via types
v1: diameter 32, hole 16, Top Layer to Bottom Layer, tented both sides, 21 vias

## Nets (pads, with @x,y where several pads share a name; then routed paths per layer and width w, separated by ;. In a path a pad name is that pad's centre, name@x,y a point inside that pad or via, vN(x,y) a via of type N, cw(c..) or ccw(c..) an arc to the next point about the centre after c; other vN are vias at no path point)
EN: J1.2 J1.4 R1.1 R2.1 R9.1 TP8.1 U1.4 | length 1963.9
  Top Layer w10: R9.1 1440.52,640 J1.4 1443.5,640.98 R2.1 ; v1(1447.21,1051.37) U1.4@1447.21,1101.29 ; R1.1 1627.5,701.74 1641.52,687.72 J1.2
  Signal Layer 2 w10: TP8.1@1034,371 1173.52,371 J1.4 1441.52,595 1485.47,551.06 1610.56,551.06 1641.52,582.02 J1.2 ; J1.4@1439.52,645.5 1439.52,853.52 1463,877 1463,1039.14 v1@1452,1050.14
GND: C1.2 C4.1 C5.1 C6.1 C8.2 D1.1 J1.1 L1.2 NT1.2 R3.1 R8.1 TP3.1 TP9.1 | length 1116.9
  Top Layer w10: v1(529.5,994.5) 573.01,950.99 R3.1
  Signal Layer 2 w10: TP3.1 243.5,877.5 TP9.1
  Bottom Layer w10: C6.1@495,1078.06 495,1037.72 529.5,1003.22 v1(529.5,994.5)
  Bottom Layer w40: TP3.1@251,461.5 TP3.1@251.41,461.04
  other v1: 814.5,933.5 909.5,933.5 777.26,995.77 856.76,995.77 948.17,995.77 1027.67,995.77 951.76,1294 1043.17,1294 1122.67,1294 910.5,1348.5 1083,1348.5
INJ: C7.1 R3.2 R4.2 TP7.1 | length 772.2
  Top Layer w10: R3.2@1166.65,950.99 1192.54,949.6 C7.1 R4.2 R4.2@1263.22,867.22 ; v1(1191.5,839) 1235,839 R4.2@1263.22,867.22 ; R4.2@1268.01,872.01 R4.2@1263.22,867.22
  Signal Layer 2 w10: TP7.1@688.5,840.5 694.99,840.48 1155,839 v1(1191.5,839)
NetC3_2: C3.2 U1.1 | length 68.9
  Top Layer w20: 1269.81,1175 U1.1@1338.7,1177.14
NetC7_2: C7.2 R4.1 R5.2 U1.3 | length 217.8
  Top Layer w10: R5.2 1326.22,1027.98 C7.2 R4.1 ; R5.2@1333.94,1044.72 1333.94,1097.58 U1.3@1338.7,1102.34
NetC9_2: C9.2 C10.2 C11.2 NT1.1 TP2.1 | length 661.7
  Bottom Layer w40: C10.2 2510.21,629.24 TP2.1 ; C10.2@2363.53,641.24 NT1.1@2364.5,1128 ; C11.2@2367.9,889.47 C11.2@2368.01,896.97
NetQ1_1: Q1.1 R8.2 | length 81.7
  Top Layer w10: Q1.1 990.16,738 R8.2
NetQ1_2: Q1.2 TP10.1 | length 191.1
  Top Layer w10: TP10.1 883.5,726.5 903.85,726.5 Q1.2
NetQ1_3: Q1.3 R9.2 | length 118.3
  Top Layer w10: Q1.3 950.76,640 R9.2
SW: C3.1 L1.1 U1.6 | length 162.4
  Top Layer w10: C3.1 C3.1@1280.85,1231.54 ; 1424.5,1243.5 1425,1244
  Top Layer w12: C3.1@1280.85,1231.54 1292.81,1243.5 1424.5,1243.5
  Top Layer w20: 1425.08,1232.48 1428.16,1232.5
VIN: C1.1 C2.1 C8.1 C11.1 J1.3 L3.2 R1.2 TP1.1 U1.5 | length 889
  Top Layer w10: J1.3 1541.52,700.02 1567.5,726 R1.2
  Top Layer w20: U1.5@1447.62,1138.29 C2.1@1534.95,1138.29
  Signal Layer 2 w10: J1.3@1534.02,650.52 1541.52,658.02 1541.52,700.02 1658.5,817 v1(1658.5,1130) 1658.5,1179 v1@1662,1182.5
  Bottom Layer w40: 2167.5,881.27 2168.53,880.24 ; 2178.5,895 C11.1@2218.5,895
  other v1: 1657,1182.5 2168,1186 2105.5,1187.5 2166,1232.5 2105,1233.5
VIN_EMI_P: C9.1 C10.1 L3.1 TP5.1 | length 726.9
  Bottom Layer w40: 2141.36,770.5 C9.1@2230.61,770.5 ; C9.1@2230.61,780.5 C9.1@2230.61,770.5 ; C9.1 C9.1@2230.61,770.5 ; TP5.1@2519.5,319.5 2426.5,319.5 2230.61,515.39 C9.1@2230.61,770.5
Vout_N: C2.2 C4.2 C5.2 C6.2 D1.2 R2.2 R5.1 TP4.1 TP6.1 U1.2 | length 1740.8
  Top Layer w10: C5.2 C5.2@1071.55,1089.76 ; R5.1 1262.2,1072.8 ; 1500.34,1059.74 1502.75,1057.33 R2.2@1502.75,801.5
  Top Layer w20: 1258,1104.64 1293.1,1139.74 U1.2
  Signal Layer 2 w10: TP6.1 685.5,1078.5 v1@1083.5,1078.5
  Bottom Layer w10: TP4.1 310.01,1139.99 C6.2 C6.2@493.93,1142.92
  other v1: 1092,1076
pads on no net: LBL1.0

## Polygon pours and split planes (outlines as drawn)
GND on Top Layer "TOP_LAYER_GND_P116" (solid, remove dead copper, pour order 116): 1.75,1793.75 2712.25,1793.75 2712.25,1.75 2710.5,0 0,0 0,1795.5
GND on Top Layer "TOP_LAYER_GND_P106" (solid, remove dead copper, pour order 106): -554.5,1848
Vout_N on Top Layer "TOP_LAYER_VOUT_N_P094" (solid, remove dead copper, pour order 94): 1296,1231 1299.75,1227.25 1540.5,1227.25 1540.5,969 1539.5,968 1539.2,968.3 1287,968.3 1287,1222
Vout_N on Top Layer "TOP_LAYER_VOUT_N_P092" (solid, remove dead copper, pour order 92): 815.46,1057.54 152,1057.54 152,1306.5 174,1306.5 659.06,1306.5 846.06,1119.5 994.5,1119.5 994.5,1057.54
Vout_N on Top Layer "TOP_LAYER_VOUT_N_P084" (solid, remove dead copper, pour order 84): 1288,1118.36 946,1120 946,1108 946,1059 1288,1059
VIN on Top Layer "TOP_LAYER_VIN_P080" (solid, remove dead copper, pour order 80): 1482,1105.5 1480,1107.5 1480,1193.5 1488,1193.5 1566.5,1272 1577.5,1261 1577.5,1105.5 1483.5,1105.5 1481.5,1103.5 1481.5,1104.5 1480,1106
VIN on Top Layer "TOP_LAYER_VIN_P010" (solid, remove dead copper, pour order 10): 1623.62,1326.29 2631.5,1326.29 2631.5,1105.5 1508.5,1105.5 1508.5,1326.29 1605.5,1326.29
SW on Top Layer "TOP_LAYER_SW_P016" (solid, remove dead copper, pour order 16): 1408.81,1219.04 1428.16,1200.29 1428.16,1169.29 1466.34,1169.29 1466.34,1201.43 1500.5,1235.59 1500.5,1469 1408.81,1469
VIN_EMI_P on Bottom Layer "BOTTOM_LAYER_VIN_EMI_P_P078" (solid, remove dead copper, pour order 78): 2197.03,828.29 2097.5,828.29 2097.5,754.24 2197.03,754.24
VIN on Bottom Layer "BOTTOM_LAYER_VIN_P114" (solid, remove dead copper, pour order 114): 2198.5,1118.5 2079,1118.5 2079,1313.5 2119.5,1313.5 2198.5,1313.5
GND on Bottom Layer "BOTTOM_LAYER_GND_P102" (solid, remove dead copper, pour order 102): 16,1809.5 16,14 2726.5,14 2726.5,1809.5
no net on Bottom Layer "BOTTOM_LAYER_NONET_P072" (solid, remove dead copper, pour order 72): 1877.64,1223.27 1872.96,1223.27 1865,1231.24 1865,1265.24 1875.5,1275.74 2008.5,1275.74 2018,1266.24 2018,1234.24 2007.93,1224.17
GND on Signal Layer 2 "SIGNAL_LAYER_2_GND_P096" (solid, remove dead copper, pour order 96): 1.75,1793.75 1.75,-1.75 2712.25,-1.75 2712.25,1793.75
GND on Signal Layer 1 "SIGNAL_LAYER_1_GND_P108" (solid, remove dead copper, pour order 108): 16,1793.5 19.5,1790 2722,1790 2722,2.5 2726.5,-2 16,-2 16,1790 17.75,1791.75

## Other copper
Top Layer:
  pour cut-out: 1278.33,1200.5 1278.33,1208.5 1253.31,1208.5 1253.31,1200.5
  pour cut-out: 1287,1052.5 1284.5,1052.5 1299.25,1052.5 1344,1007.75 1344,889.93 1299.07,845 1285.5,845 1247.5,883 1247.5,1015.5 1284.5,1052.5
Signal Layer 2:
  region net GND: 958,1169.5
Bottom Layer:
  rectangle net VIN: 2080,855.74 2197.03,1201
  rectangle net VIN_EMI_P: 2068.53,747.74 2197.03,831.24
  pour cut-out: 1984.5,1162.6 2712.12,1161.39 2710.5,0 1984.5,0

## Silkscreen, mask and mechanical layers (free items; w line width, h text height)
Top Overlay:
  lines w10: 1315.5,225 1945.07,225 1945.07,510.5 1315.5,510.5 1315.5,225
  text "VIN" at 2469,1426.5 h36
  text "VOUT_N" at 357,1403.5 h36
  text "VOUT_N" at 384.5,1136.5 h36
  text "INJ" at 657.5,938.5 h36
  text "GND" at 346.5,821 h36
  text "GND" at 2491,779 h36
  text "3" at 1536.5,540.5 h30
  text "1" at 1733,540.5 h30
  text "4" at 1421.5,539 h30
  text "2" at 1632.5,537.5 h30
  text "<JUMPER SETTING>" at 1338,455.5 h30
  text "EN_EXT" at 724,428.5 h36
  text "2&3 -> EN=VIN" at 1338,393 h30
  text "GND" at 399.5,392 h36
  text "EN" at 1169.5,335.5 h36
  text "1&2 -> EN=GND" at 1338,332.53 h30
  text "OPEN -> EN to Divider" at 1335.5,267.5 h30
  text "VEMI" at 2465.5,174 h36
Bottom Solder:
  rectangle: 2069.03,754.24 2197.03,828.29
  rectangle: 2068.53,855.74 2197.03,939.24
M1 Board Outline:
  lines w10: 0,0 0,1795.5 2710.5,1795.5 2710.5,0 0,0
M2 Board Dimensions:
  rectangle: 125,-400 500,-275
  rectangle: 0,-275 125,-150
  lines w7: 0,-275 1000,-275 ; 125,-400 125,-150 ; 250,-400 250,-150 ; 500,-400 500,-150 ; 750,-400 750,-150 ; 0,-400 0,-150 1000,-150 1000,-400 0,-400
M5 Assembly Top:
  lines w10: -292,-930.17 6308,-930.17 ; -292,-726.83 6310,-726.83 ; -292,-523.5 -292,-1133.5 3713,-1133.5 6310,-1133.5 6310,-523.5 -291.5,-523.5 -291.5,-1133.5 1284,-1133.5 ; 2173,-1133.5 2173,-523.5 ; 3440,-726.83 3440,-523.5 ; 4280,-726.83 4280,-523.5 ; 4902,-1140 4902,-937.17
  text "COMPONENTS MARKED 'DNP' SHOULD NOT BE POPULATED." at 1153.5,-318.5 h60
  text "ASSEMBLY VARIANT:" at 1153,-434 h60
  text ".VariantName" at 2189,-434 h60
  text "PCB VIEWED FROM TOP SIDE" at -228.5,-655.67 h60
  text "BOARD #:" at 2248,-655.67 h60
  text ".PRJ_Number" at 2793.5,-655.67 h60
  text "REV:" at 3638,-655.67 h60
  text ".PCB_Rev" at 3929.5,-655.67 h60
  text "SVN REV:" at 4476,-655.67 h60
  text ".VersionControl_RevNumber" at 4982,-655.67 h60
  text "TID #:" at 2248,-859 h60
  text ".TID" at 2793.5,-859 h60
  text "PLOT NAME =" at -228.5,-1064.34 h60
  text ".plot_File_Name" at 577,-1064.34 h60
  text "GENERATED    :" at 2250,-1064.34 h60
  text ".Print_Date" at 3119.5,-1064.34 h60
  text ".Print_Time" at 3848.5,-1064.34 h60
  text "TEXAS INSTRUMENTS" at 5113,-1064.34 h60
M6 Assembly Bottom:
  lines w10: -292.5,-727.33 6309.5,-727.33 ; -290.5,-930.67 6309.5,-930.67 ; 1115.5,-1140.5 1115.5,-937.67 ; 1737.5,-727.33 1737.5,-524 ; 2577.5,-727.33 2577.5,-524 ; 3844.5,-1134 3844.5,-524 ; 4733.5,-1134 6309,-1134 6309,-524 -292.5,-524 -292.5,-1134 2304.5,-1134 6309.5,-1134 6309.5,-524
  text "COMPONENTS MARKED 'DNP' SHOULD NOT BE POPULATED." at 6102,-318 h60
  text ".VariantName" at 5058,-434 h60
  text "ASSEMBLY VARIANT:" at 6097,-434 h60
  text ".VersionControl_RevNumber" at 1035.5,-656.17 h60
  text "SVN REV:" at 1541.5,-656.17 h60
  text ".PCB_Rev" at 2088,-656.17 h60
  text "REV:" at 2379.5,-656.17 h60
  text ".PRJ_Number" at 3224,-656.17 h60
  text "BOARD #:" at 3769.5,-656.17 h60
  text "PCB VIEWED FROM BOTTOM SIDE" at 6246,-656.17 h60
  text ".TID" at 3224,-859.5 h60
  text "TID #:" at 3769.5,-859.5 h60
  text "TEXAS INSTRUMENTS" at 904.5,-1064.84 h60
  text ".Print_Time" at 2169,-1064.84 h60
  text ".Print_Date" at 2898,-1064.84 h60
  text "GENERATED    :" at 3767.5,-1064.84 h60
  text ".plot_File_Name" at 5440.5,-1064.84 h60
  text "PLOT NAME =" at 6246,-1064.84 h60
M9 Title Sheet:
  drawing of 57 lines, arcs and shapes, not listed
  text "1" at 739.84,8036.5 h70
  text "2" at 3235.5,8036.5 h70
  text "3" at 5724.84,8036.5 h70
  text "4" at 8231.51,8036.5 h70
  text "5" at 10730.5,8036.5 h70
  text "6" at 13235.5,8036.5 h70
  text "A" at -416.5,6893.5 h70
  text "A" at 14383.5,6893.5 h70
  text "B" at -416.5,4513.5 h70
  text "B" at 14383.5,4513.5 h70
  text "C" at -416.5,2138.5 h70
  text "C" at 14383.5,2138.5 h70
  text "PROJECT TITLE:" at 11343.5,277.5 h45
  text ".PRJ_Title" at 11393.5,144.17 h70
  text "DESIGNED FOR:" at 11343.5,-23.5 h45
  text ".PRJ_Customer" at 11393.5,-163.5 h70
  text "D" at -416.5,-231.5 h70
  text "D" at 14383.5,-231.5 h70
  text "FILE NAME:" at 11343.5,-323.5 h45
  text ".PCB_File_Name_No_Path" at 11393.5,-443.5 h70
  text "Texas Instruments (TI) and/or its licensors do not warrant the accuracy or completeness of this specification" at 6374,-605.34 h45
  text "ENGINEER:" at 11343.5,-613.5 h45
  text "LAYOUT BY:" at 12848.5,-613.5 h45
  text "or any information contained therein. TI and/or its licensors do not warrant that this design will meet" at 6329.01,-718 h45
  text ".PRJ_Engineer" at 11393.5,-768.49 h70
  text ".PCB_Layout" at 12899,-768.49 h70
  text "the specifications, will be suitable for your application or fit for any particular purpose, or will operate in" at 6329.01,-830.67 h45
  text "ALTIUM DESIGNER VERSION:" at 12848.5,-923.5 h45
  text "an implementation. TI and/or its licensors do not warrant that the design is production worthy. You should" at 6329.01,-943.33 h45
  text "completely validate and test your design implementation to confirm the system functionality for your application." at 6374,-1056 h45
  text ".print_Scale" at 11393.5,-1056.83 h70
  text ".Application_BuildNumber" at 12899,-1056.83 h70
  text "1" at 739.84,-1263.5 h70
  text "2" at 3235.5,-1263.5 h70
  text "3" at 5724.84,-1263.5 h70
  text "4" at 8231.51,-1263.5 h70
  text "5" at 10730.5,-1263.5 h70
  text "6" at 13235.5,-1263.5 h70
M10 Fab Notes:
  drawing of 173 lines, arcs and shapes, not listed
  text "DESIGN INFORMATION" at 12378.02,6201 h60
  text "MIN. TRACK WIDTH:" at 11733.46,6021 h60
  text "8" at 12829.7,6021 h60
  text "MIL" at 12984.46,6021 h60
  text "MIN. CLEARANCE:" at 11733.46,5889 h60
  text "0.2" at 12769.7,5889 h60
  text "mm" at 12984.46,5889 h60
  text "MIN. VIA PAD SIZE:" at 11733.46,5757 h60
  text "24" at 12799.71,5757 h60
  text "MIL" at 12984.46,5757 h60
  text "0.05mm (2MIL)" at 12428.46,5615.29 h60
  text "MINIMUM ANNULAR RING" at 11404.23,5611 h60
  text "EXTERNAL" at 13136.46,5611 h60
  text "PER" at 11604.23,5493 h60
  text "IPC-D-275 CLASS 2 LEVEL C" at 11824.23,5493 h60
  text "MIL, HOLES" at 13312.46,5380.71 h60
  text "+/-" at 12920,5380 h60
  text "+/-" at 13774,5380 h60
  text "REGISTRATION TOLERANCES:" at 11404.23,5375 h60
  text "METAL" at 12604,5375 h60
  text "5" at 13180.2,5375 h60
  text "3" at 14013.2,5375 h60
  text "MIL" at 14129.46,5375 h60
  text "+/-" at 13774,5262 h60
  text "HOLE SIZE TOLERANCE (UNLESS OTHERWISE SPECIFIED):" at 11404.23,5257 h60
  text "3" at 14013.2,5257 h60
  text "MIL" at 14129.46,5257 h60
  text "MATERIAL:" at 11329.46,5047.54 h60
  text "FR-4 High Tg" at 12315.9,4907.21 h60
  text "FR-408" at 11750.46,4898.64 h60
  text "OTHER" at 13238.46,4898.64 h60
  text "X" at 12161,4895 h60
  text "62 MIL (1.6mm) +/-10%" at 12070.56,4735.92 h60
  text "THICKNESS:" at 11404.23,4731.64 h60
  text "X" at 11942.4,4731.64 h60
  text "OTHER" at 13355.46,4731.64 h60
  text "TOLERANCE:" at 11404.23,4573.64 h60
  text "X" at 12243.53,4573.64 h60
  text "ANSI IPC-6012 TYPE 3 CLASS 2" at 12430.48,4573.64 h60
  text "OTHER +/-" at 12430.46,4417.64 h60
  text "BOW & TWIST:" at 11404.23,4260.64 h60
  text "X" at 12243.53,4260.64 h60
  text "ANSI IPC-6012 TYPE 3 CLASS 2" at 12430.48,4260.64 h60
  text "OTHER +/-" at 12430.46,4102.13 h60
  text "DRILLING:" at 11329.46,3963.64 h60
  text "REFERENCE:" at 11404.23,3846.64 h60
  text "X" at 12052.46,3846.64 h60
  text "AS SHOWN" at 12239.46,3846.64 h60
  text "X" at 12953.46,3846.64 h60
  text "NC_DRILL FILES" at 13090.46,3846.64 h60
  text "PTH COPPER THICKNESS:" at 11404.23,3688.64 h60
  text "X" at 12534.46,3688.64 h60
  text "20-30 um" at 12671.46,3688.64 h60
  text "OTHER" at 13388.46,3688.64 h60
  text "BOARD FINISH:" at 11329.46,3529.64 h60
  text "SILKSCREEN:" at 11484.68,3411.64 h60
  text "X" at 12433.46,3411.64 h60
  text "TOP" at 12559.46,3411.64 h60
  text "X" at 12943.46,3411.64 h60
  text "BOTTOM" at 13070.46,3411.64 h60
  text "SILKSCREEN COLOR:" at 11484.68,3244.64 h60
  text "X" at 12432.42,3244.64 h60
  text "WHITE" at 12559.46,3244.64 h60
  text "OTHER" at 13070.46,3244.64 h60
  text "X" at 12563.42,3085.44 h60
  text "GREEN" at 12690.46,3085.44 h60
  text "OTHER" at 13308.46,3085.44 h60
  text "SOLDER RESIST COLOR:" at 11484.68,3074.64 h60
  text "X" at 12563.42,2915.44 h60
  text "MATTE" at 12690.46,2915.44 h60
  text "SEMI-GLOSS" at 13308,2914.8 h60
  text "IMMERSION GOLD (ENIG)" at 12390.46,2726.92 h60
  text "ENEPIG" at 13728,2723.64 h60
  text "SURFACE FINISH:" at 11329.46,2722.64 h60
  text "X" at 12203.51,2722.64 h60
  text "IMM. TIN/SILVER OR EQUIV" at 11659,2565.64 h60
  text "OTHER" at 13090.46,2565.64 h60
  text "ARRAY/PANEL:" at 11329.46,2386.64 h60
  text "CUT AND TRIM PER M1 BOARD OUTLINE" at 12390.46,2382.35 h60
  text "N.C. ROUTE" at 12390.46,2230.64 h60
  text "X" at 13069.46,2230.64 h60
  text "V. SCORE" at 13256.46,2230.64 h60
  text "CERTIFICATION:" at 11329.46,2093.64 h60
  text "MATERIALS AND WORKMANSHIP FOR ALL PCBS" at 12054.46,2093.64 h60
  text "TO MEET OR EXCEED THE REQUIREMENTS OF:" at 12054.46,1995.64 h60
  text "X" at 11680.96,1859.13 h60
  text "ANSI IPC-A-600F CLASS ->" at 11819.96,1859.13 h60
  text "X" at 13459.02,1859.13 h60
  text "2" at 13577.96,1859.14 h60
  text "1" at 13262.96,1857.64 h60
  text "3" at 13931.96,1857.64 h60
  text "X" at 12495.02,1699.64 h60
  text "RoHS" at 12631.96,1699.64 h60
  text "OTHER" at 13276.36,1699.64 h60
  text "PER ORDER" at 13673.42,1699.64 h60
  text "ALL BOARDS MUST MEET OR EXCEED UL94-V0 REQUIREMENTS." at 11357,1534 h60
  text "PCB MUST BEAR THE UL94V-0 UL REGISTERED MATERIAL ID NUMBER" at 11357,1414 h60
  text "ADDITIONAL REQUIREMENTS:" at 11329.46,1240.64 h60
  text "MICROSECTION:" at 11404.23,1125.64 h60
  text "YES" at 12309.96,1125.64 h60
  text "REQUIRED" at 13171.46,969.49 h60
  text "BARE BOARD ELEC. TEST:" at 11404.23,966.64 h60
  text "NONE" at 12709.96,966.64 h60
  text "X" at 13044.46,966.64 h60
  text "PER ORDER" at 13763.46,966.64 h60
M11 Gerber Information:
  lines w10: -292,-930.17 6308,-930.17 ; -292,-726.83 6310,-726.83 ; -292,-523.5 -292,-1133.5 3713,-1133.5 6310,-1133.5 6310,-523.5 -291.5,-523.5 -291.5,-1133.5 1284,-1133.5 ; 2173,-1133.5 2173,-523.5 ; 3440,-726.83 3440,-523.5 ; 4280,-726.83 4280,-523.5 ; 4902,-1140 4902,-937.17
  text "ALL ARTWORK VIEWED FROM TOP SIDE" at -228.5,-655.67 h60
  text "BOARD #:" at 2248,-655.67 h60
  text ".PRJ_Number" at 2793.5,-655.67 h60
  text "REV:" at 3638,-655.67 h60
  text ".PCB_Rev" at 3929.5,-655.67 h60
  text "SVN REV:" at 4476,-655.67 h60
  text ".VersionControl_RevNumber" at 4982,-655.67 h60
  text "LAYER NAME =" at -228.5,-858.49 h60
  text "TID #:" at 2248,-859 h60
  text ".TID" at 2793.5,-859 h60
  text "PLOT NAME =" at -228.5,-1064.34 h60
  text ".plot_File_Name" at 577,-1064.34 h60
  text "GENERATED    :" at 2250,-1064.34 h60
  text ".Print_Date" at 3119.5,-1064.34 h60
  text ".Print_Time" at 3848.5,-1064.34 h60
  text "TEXAS INSTRUMENTS" at 5113,-1064.34 h60
M12 Stackup:
  drawing of 269 lines, arcs and shapes, not listed
  text "Layer" at 2707.55,6065 h60
  text "Name" at 3117.47,6065 h60
  text "Material" at 4057.21,6065 h60
  text "Thickness" at 4916.97,6065 h60
  text "Constant" at 5566.81,6065 h60
  text "Board Layer Stack" at 6136.67,6065 h60
  text "1" at 2707.55,5945 h60
  text "Top Overlay" at 3117.47,5945 h60
  text "2" at 2707.55,5825 h60
  text "Top Solder" at 3117.47,5825 h60
  text "Solder Resist" at 4057.21,5825 h60
  text "0.40mil" at 4916.97,5825 h60
  text "3.5" at 5566.81,5825 h60
  text "3" at 2707.55,5705 h60
  text "Top Layer" at 3117.47,5705 h60
  text "Copper" at 4057.21,5705 h60
  text "2.80mil" at 4916.97,5705 h60
  text "4" at 2707.55,5585 h60
  text "Dielectric1" at 3117.47,5585 h60
  text "FR-4 High Tg" at 4057.21,5585 h60
  text "10.00mil" at 4916.97,5585 h60
  text "4.8" at 5566.81,5585 h60
  text "5" at 2707.55,5465 h60
  text "Signal Layer 1" at 3117.47,5465 h60
  text "Copper" at 4057.21,5465 h60
  text "1.42mil" at 4916.97,5465 h60
  text "6" at 2707.55,5345 h60
  text "Dielectric 2" at 3117.47,5345 h60
  text "FR-4 High Tg" at 4057.21,5345 h60
  text "32.00mil" at 4916.97,5345 h60
  text "4.2" at 5566.81,5345 h60
  text "7" at 2707.55,5225 h60
  text "Signal Layer 2" at 3117.47,5225 h60
  text "Copper" at 4057.21,5225 h60
  text "1.42mil" at 4916.97,5225 h60
  text "8" at 2707.55,5105 h60
  text "Dielectric 3" at 3117.47,5105 h60
  text "FR-4 High Tg" at 4057.21,5105 h60
  text "10.00mil" at 4916.97,5105 h60
  text "4.2" at 5566.81,5105 h60
  text "9" at 2707.55,4985 h60
  text "Bottom Layer" at 3117.47,4985 h60
  text "Copper" at 4057.21,4985 h60
  text "2.80mil" at 4916.97,4985 h60
  text "10" at 2707.55,4865 h60
  text "Bottom Solder" at 3117.47,4865 h60
  text "Solder Resist" at 4057.21,4865 h60
  text "0.40mil" at 4916.97,4865 h60
  text "3.5" at 5566.81,4865 h60
Drill Drawing:
  circle w10: c2734.99,4357.83 r27.63
  lines w10: 2707.36,4205.88 2762.62,4205.88 2762.62,4261.13 2707.36,4261.13 2707.36,4205.88 ; 2707.36,4509.77 2762.62,4509.77 2734.99,4454.52 2707.36,4509.77 ; 2707.36,4592.65 2721.18,4592.65 2734.99,4578.84 2748.8,4592.65 2762.62,4592.65 2748.8,4606.47 2762.62,4620.28 2748.8,4620.28 2734.99,4634.09 2721.18,4620.28 2707.36,4620.28 2721.18,4606.47 2707.36,4592.65 ; 2707.36,4703.16 2734.99,4716.97 2762.62,4703.16 2748.8,4730.79 2762.62,4758.41 2734.99,4744.6 2707.36,4758.41 2721.18,4730.79 2707.36,4703.16
  lines w12: 2657.27,4168.58 9714.8,4168.58 ; 2657.27,4790.18 9714.8,4790.18 ; 2995.14,4044.26 2995.14,4914.5 ; 3327.14,4044.26 3327.14,4914.5 ; 3963.7,4044.26 3963.7,4914.5 ; 4222.84,4044.26 4222.84,4914.5 ; 4598,4044.26 4598,4914.5 ; 5322.33,4044.26 5322.33,4914.5 ; 5851.47,4044.26 5851.47,4914.5 ; 6154.76,4044.26 6154.76,4914.5 ; 6551.43,4044.26 6551.43,4914.5 ; 6904.81,4044.26 6904.81,4914.5 ; 7324.72,4044.26 7324.72,4914.5 ; 7951.56,4044.26 7951.56,4914.5 ; 8562.22,4044.26 8562.22,4914.5 ; 8999.98,4044.26 8999.98,4914.5 ; 2657.27,4044.26 9714.8,4044.26 9714.8,4914.5 2657.27,4914.5 2657.27,4044.26
  text "Symbol" at 2731.87,4827.48 h72
  text "Quantity" at 3032.43,4827.48 h72
  text "Finished Hole Size" at 3364.43,4827.48 h72
  text "Plated" at 4001,4827.48 h72
  text "Hole Type" at 4260.14,4827.48 h72
  text "Drill Layer Pair" at 4635.29,4827.48 h72
  text "Hole Tolerance" at 5359.63,4827.48 h72
  text "Via/Pad" at 5888.76,4827.48 h72
  text "Pad Shape" at 6192.06,4827.48 h72
  text "Template" at 6588.73,4827.48 h72
  text "Description" at 6942.11,4827.48 h72
  text "Hole Tolerance (+)" at 7362.02,4827.48 h72
  text "Hole Tolerance (-)" at 7988.86,4827.48 h72
  text "Hole Length" at 8599.52,4827.48 h72
  text "Routed Path Length" at 9037.28,4827.48 h72
  text "3" at 3032.43,4703.16 h60
  text "10.00mil (0.254mm)" at 3364.43,4703.16 h60
  text "PTH" at 4001,4703.16 h60
  text "Round" at 4260.14,4703.16 h60
  text "Top Layer - Bottom Layer" at 4635.29,4703.16 h60
  text "Via" at 5888.76,4703.16 h60
  text "Rounded" at 6192.06,4703.16 h60
  text "(Mixed)" at 6588.73,4703.16 h60
  text "-" at 8599.52,4703.16 h60
  text "-" at 9037.28,4703.16 h60
  text "20" at 3032.43,4578.84 h60
  text "16.00mil (0.406mm)" at 3364.43,4578.84 h60
  text "PTH" at 4001,4578.84 h60
  text "Round" at 4260.14,4578.84 h60
  text "Top Layer - Bottom Layer" at 4635.29,4578.84 h60
  text "Via" at 5888.76,4578.84 h60
  text "Rounded" at 6192.06,4578.84 h60
  text "(Mixed)" at 6588.73,4578.84 h60
  text "-" at 8599.52,4578.84 h60
  text "-" at 9037.28,4578.84 h60
  text "4" at 3032.43,4454.52 h60
  text "40.00mil (1.016mm)" at 3364.43,4454.52 h60
  text "PTH" at 4001,4454.52 h60
  text "Round" at 4260.14,4454.52 h60
  text "Top Layer - Bottom Layer" at 4635.29,4454.52 h60
  text "Pad" at 5888.76,4454.52 h60
  text "(Mixed)" at 6192.06,4454.52 h60
  text "(Mixed)" at 6588.73,4454.52 h60
  text "-" at 8599.52,4454.52 h60
  text "-" at 9037.28,4454.52 h60
  text "5" at 3032.43,4330.2 h60
  text "63.00mil (1.600mm)" at 3364.43,4330.2 h60
  text "PTH" at 4001,4330.2 h60
  text "Round" at 4260.14,4330.2 h60
  text "Top Layer - Bottom Layer" at 4635.29,4330.2 h60
  text "Pad" at 5888.76,4330.2 h60
  text "Rounded" at 6192.06,4330.2 h60
  text "c221h160" at 6588.73,4330.2 h60
  text "-" at 8599.52,4330.2 h60
  text "-" at 9037.28,4330.2 h60
  text "5" at 3032.43,4205.88 h60
  text "98.43mil (2.500mm)" at 3364.43,4205.88 h60
  text "PTH" at 4001,4205.88 h60
  text "Round" at 4260.14,4205.88 h60
  text "Top Layer - Bottom Layer" at 4635.29,4205.88 h60
  text "Pad" at 5888.76,4205.88 h60
  text "Rounded" at 6192.06,4205.88 h60
  text "c350h250" at 6588.73,4205.88 h60
  text "-" at 8599.52,4205.88 h60
  text "-" at 9037.28,4205.88 h60
  text "37 Total" at 3032.43,4081.56 h60
M17 Embedded Cavity:
  text ".Layer_Name" at 577,-858.49 h60
M18 Embedded Assembly:
  text ".Layer_Name" at 577,-858.49 h60
M19 Embedded Keepout:
  text ".Layer_Name" at 577,-858.49 h60

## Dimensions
0,0 to 0,1795.5 on M2 Board Dimensions
0,-400 to 1000,-400 on M2 Board Dimensions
